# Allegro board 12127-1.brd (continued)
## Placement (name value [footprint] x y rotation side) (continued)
PR106  100KR2F-L1-GP  [R402H16]  127.2 43.27 0 top
PR109  10KR2J-3-GP  [R402H16]  126.03 44.21 180 top
PR110  2D2R5J-1-GP  [R805H24]  124.43 55.85 90 top
PR111  2D2R5J-1-GP  [R805H24]  124.61 49.53 270 top
PR126  10KR2J-3-GP  [R402H16]  115.01 56.31 180 top
PR127  2D2R5J-1-GP  [R805H24]  113.21 55.12 180 top
PR134  100KR2F-L1-GP  [R402H16]  67.59 31.75 90 top
PU8  RT8237CZQW-2-GP  [DFN10G3-G265175H32]  128.8 46.94 180 top
PWCLR1  PIN-CON3-S-GP  [21S-91-03GB01]  107.82 30.48 180 top
Q4  2N7002K-1-GP  [SOT23DGS2D4H44]  111.12 215.26 90 top
Q5  2N7002K-1-GP  [SOT23DGS2D4H44]  116.2 222.5 0 top
Q6  AO3413-GP-U  [SOT23DGS2D8H50]  188.82 223.28 90 top
Q9  AZ5125-02S-R7G-GP  [SOT23-2D4-312H46]  6.68 212.8 180 top
Q10  AZ5125-02S-R7G-GP  [SOT23-2D4-312H46]  6.27 207.09 270 top
Q11  AZ5125-02S-R7G-GP  [SOT23-2D4-312H46]  45.36 219.3 90 top
Q12  MMBT3904-4-GP  [SOT23CBE2D4H44]  84.54 193.53 270 top
Q13  SIR172ADP-T1-GE3-GP  [PPAK-5PH45]  127.43 205.33 0 top
Q14  AZ5125-02S-R7G-GP  [SOT23-2D4-312H46]  44.19 227.79 270 top
Q15  SIRA12DP-T1-GE3-GP  [PPAK-5PH45]  131.98 188.54 90 top
Q16  SIR172ADP-T1-GE3-GP  [PPAK-5PH45]  121.11 205.33 0 top
Q17  AZ5125-02S-R7G-GP  [SOT23-2D4-312H46]  44.17 237.92 90 top
Q22  SIRA12DP-T1-GE3-GP  [PPAK-5PH45]  96.37 194.51 270 top
Q23  SIRA12DP-T1-GE3-GP  [PPAK-5PH45]  96.24 186.06 270 top
Q26  SIR172ADP-T1-GE3-GP  [PPAK-5PH45]  96.55 203 0 top
Q27  SIR172ADP-T1-GE3-GP  [PPAK-5PH45]  165.61 191.85 0 top
Q28  SIRA12DP-T1-GE3-GP  [PPAK-5PH45]  177.11 183.59 90 top
Q29  SIRA12DP-T1-GE3-GP  [PPAK-5PH45]  132.03 197 90 top
Q30  SIRA12DP-T1-GE3-GP  [PPAK-5PH45]  177.11 175.34 90 top
Q31  SIR172ADP-T1-GE3-GP  [PPAK-5PH45]  171.93 191.85 0 top
Q32  SIR172ADP-T1-GE3-GP  [PPAK-5PH45]  102.9 202.98 0 top
Q34  SIR172ADP-T1-GE3-GP  [PPAK-5PH45]  118.82 52.2 180 top
Q35  SIRA12DP-T1-GE3-GP  [PPAK-5PH45]  68.96 48.26 0 top
Q37  MMDT3904-7-F-1-GP  [SOT-363H44]  165.52 160.65 180 top
Q38  2N7002K-2-GP  [SOT23DGS2D4H44]  97.79 48.69 180 top
Q39  AO3413-GP-U  [SOT23DGS2D8H50]  5.99 111.24 0 top
Q40  MMDT3904-7-F-1-GP  [SOT-363H44]  189.52 120.31 90 top
Q42  MMDT3904-7-F-1-GP  [SOT-363H44]  175.97 59.46 180 top
Q43  SIRA12DP-T1-GE3-GP  [PPAK-5PH45]  125.27 60.05 90 top
Q44  MMBT3904-4-GP  [SOT23CBE2D4H44]  8.41 183.64 270 top
Q45  MMBT3904-4-GP  [SOT23CBE2D4H44]  176.89 52.04 0 top
Q46  AO3413-GP-U  [SOT23DGS2D8H50]  171.25 36.58 90 top
Q47  AO3413-GP-U  [SOT23DGS2D8H50]  171.25 32.94 90 top
Q48  MMDT3904-7-F-1-GP  [SOT-363H44]  8.33 179.1 90 top
Q49  MMDT3904-7-F-1-GP  [SOT-363H44]  176.86 36.17 180 top
Q50  MMDT3904-7-F-1-GP  [SOT-363H44]  170.03 49.67 90 top
Q51  QM3006D-GP  [SMD-TO-252-DGS6698H99]  178.46 43.21 90 top
Q53  MMBT3904-4-GP  [SOT23CBE2D4H44]  64.9 58.93 0 top
Q54  2N7002-11-GP  [SOT23DGS2D4H44]  159.33 164.37 270 top
Q55  MMDT3904-7-F-1-GP  [SOT-363H44]  70.99 30.73 0 top
Q56  2N7002-11-GP  [SOT23DGS2D4H44]  161.92 160.8 270 top
Q57  MMBT3904-4-GP  [SOT23CBE2D4H44]  105.13 35.68 90 top
Q58  2N7002K-1-GP  [SOT23DGS2D4H44]  181.99 50.55 0 top
Q59  MMBT3904-4-GP  [SOT23CBE2D4H44]  18.72 15.52 90 top
Q60  MMBT3904-4-GP  [SOT23CBE2D4H44]  22.53 15.52 90 top
Q61  MMBT3904-4-GP  [SOT23CBE2D4H44]  53.77 43.79 0 top
Q62  MMDT3904-7-F-1-GP  [SOT-363H44]  14.07 16.54 270 top
Q64  MMDT3904-7-F-1-GP  [SOT-363H44]  184.53 215.77 180 top
Q67  MMDT3904-7-F-1-GP  [SOT-363H44]  69.93 69.42 180 top
Q69  2N7002DW-6-GP  [SOT-363H44]  137.92 45.85 90 top
Q70  MMBT3904-4-GP  [SOT23CBE2D4H44]  177.57 31.32 90 top
Q71  MMBT3904-4-GP  [SOT23CBE2D4H44]  18.72 11.86 90 top
Q72  MMBT3904-4-GP  [SOT23CBE2D4H44]  22.53 11.86 90 top
Q73  2N7002DW-6-GP  [SOT-363H44]  138.1 42.32 180 top
Q74  MMBT3904-4-GP  [SOT23CBE2D4H44]  188.63 116.88 270 top
Q77  2N7002K-1-GP  [SOT23DGS2D4H44]  60.53 71.62 90 top
Q78  2N7002K-1-GP  [SOT23DGS2D4H44]  64.22 71.62 0 top
Q79  MMBT3904-4-GP  [SOT23CBE2D4H44]  108.97 6.48 90 top
Q80  2N7002K-1-GP  [SOT23DGS2D4H44]  113.79 6.48 90 top
Q82  MMBT3906-4-GP  [SOT23CBE2D4H44]  10.03 55.8 270 top
Q89  AO3401A-GP  [SOT23DGS2D8H50]  158.75 18.16 90 top
Q90  AO3401A-GP  [SOT23DGS2D8H50]  164.59 18.41 0 top
Q108  MMBT3904DW-GP  [SOT-363H44]  5.61 102.59 0 top
Q109  MMBT3904-4-GP  [SOT23CBE2D4H44]  191.64 219.58 0 top
Q110  MMBT3904-4-GP  [SOT23CBE2D4H44]  188.06 219.58 0 top
QF2  MMDT3904-7-F-1-GP  [SOT-363H44]  53.34 18.54 270 top
R3  1KR2J-1-GP  [R402H16]  31.5 221.49 90 top
R4  1KR2J-1-GP  [R402H16]  28.96 221.49 90 top
R5  20KR2F-L-GP  [R402H16]  28.68 233.83 180 top
R6  22KR2J-GP  [R402H16]  31.5 222.63 270 top
R7  22KR2J-GP  [R402H16]  28.96 222.63 270 top
R8  39K2R2F-L-GP  [R402H16]  27.64 233.83 180 top
R9  2K2R2J-2-GP  [R402H16]  31.5 223.77 90 top
R10  2K2R2J-2-GP  [R402H16]  28.96 223.77 90 top
R11  0R0603-PAD-2-GP  [0R0603-PAD-1]  63.37 237.11 90 bottom
R12  20KR2F-L-GP  [R402H16]  21.26 237.97 180 top
R13  100R2F-L1-GP-U  [R402H14]  89.53 231.27 180 top
R14  100R2F-L1-GP-U  [R402H14]  87 228.73 270 top
R15  2K2R2J-2-GP  [R402H16]  84.84 224.41 270 top
R16  2K2R2J-2-GP  [R402H16]  89.03 228.73 270 top
R17  2K2R2J-2-GP  [R402H16]  111.25 223.14 270 top
R18  2K2R2J-2-GP  [R402H16]  113.16 223.14 90 top
R19  2KR2F-3-GP  [R402H16]  185.24 220.47 180 top
R20  20KR2F-L-GP  [R402H16]  16.15 54.46 0 top
R21  1KR2J-1-GP  [R402H16]  183.24 218.47 90 top
R24  10KR2J-3-GP  [R402H16]  10.97 178.38 180 top
R25  5K1R2J-4-GP  [R402H16]  10.97 180.34 180 top
R26  75R2F-2-GP  [R402H16]  35.89 220.5 90 top
R27  4K7R2J-2-GP  [R402H16]  35.89 221.51 90 top
R29  0R3J-0-U-GP  [R603H22]  11.99 224.79 0 top
R30  150R2F-1-GP  [R402H16]  71.88 224.54 90 top
R31  150R2F-1-GP  [R402H16]  74.8 224.54 90 top
R32  150R2F-1-GP  [R402H16]  77.72 224.54 90 top
R33  499R2F-2-GP  [R402H16]  14.73 30.86 270 top
R34  499R2F-2-GP  [R402H16]  14.73 29.84 270 top
R41  100KR2F-L1-GP  [R402H16]  112.39 217.55 90 top
R43  22KR2J-GP  [R402H16]  39.5 225.02 180 top
R44  22KR2J-GP  [R402H16]  40.51 225.02 180 top
R45  2K2R2J-2-GP  [R402H16]  53.21 24.05 180 top
R48  75R2F-2-GP  [R402H16]  33.99 220.5 270 top
R49  4K7R2J-2-GP  [R402H16]  33.99 221.51 270 top
R50  2K2R2J-2-GP  [R402H16]  111.89 222.12 90 top
R51  2K2R2J-2-GP  [R402H16]  110.49 217.55 270 top
R52  75R2F-2-GP  [R402H16]  39.5 222.5 180 top
R53  75R2F-2-GP  [R402H16]  40.51 222.5 180 top
R57  470R2J-2-GP  [R402H16]  100.08 220.66 0 top
R58  470R2J-2-GP  [R402H16]  101.46 220.67 0 top
R59  470R2J-2-GP  [R402H16]  102.64 220.66 0 top
R60  470R2J-2-GP  [R402H16]  103.97 220.67 0 top
R61  470R2J-2-GP  [R402H16]  105.16 220.66 0 top
R62  470R2J-2-GP  [R402H16]  106.54 220.67 0 top
R63  470R2J-2-GP  [R402H16]  107.64 220.66 0 top
R64  470R2J-2-GP  [R402H16]  109.03 220.67 0 top
R65  2K2R2J-2-GP  [R402H16]  83.44 226.57 180 top
R66  2K2R2J-2-GP  [R402H16]  86.74 224.41 270 top
R67  20KR2F-L-GP  [R402H16]  116.08 224.92 270 top
R68  20KR2F-L-GP  [R402H16]  13.65 222.92 0 top
R69  0R3J-0-U-GP  [R603H22]  188.98 225.65 270 top
R70  1KR2J-1-GP  [R402H16]  193.32 223.09 270 top
R71  0R2J-2-GP  [R402H16]  48.13 18.92 270 top
R72  4K7R2J-2-GP  [R402H16]  19.15 29.84 180 top
R73  5K1R2J-4-GP  [R402H16]  14.69 222.92 0 top
R74  33R2J-2-GP  [R402H16]  12.45 228.22 270 top
R75  47R2F-GP  [R402H16]  16.89 211.46 0 top
R76  75R2F-2-GP  [R402H16]  43.26 221.13 90 top
R77  22KR2J-GP  [R402H16]  43.26 222.17 270 top
R78  1MR2J-1-GP  [R402H16]  117.22 220.09 270 top
R79  10KR2F-2-GP  [R402H16]  15.76 222.92 0 top
R80  0R0603-PAD-1-GP  [0R0603-PAD]  159.49 202.44 180 top
R82  1KR2J-1-GP  [R402H16]  188.44 216.76 180 top
R83  4K7R2J-2-GP  [R402H16]  13.34 35.18 0 top
R84  1KR2J-1-GP  [R402H16]  171.07 156.74 90 top
R87  2D2R5J-1-GP  [R805H24]  170.51 166.34 90 top
R88  1KR2J-1-GP  [R402H16]  180.85 167.54 0 top
R90  22KR2J-GP  [R402H16]  15.88 211.46 180 top
R91  75R2F-2-GP  [R402H16]  44.02 215.77 90 top
R92  22KR2J-GP  [R402H16]  43.99 216.81 270 top
R93  120KR2F-L-GP  [R402H16]  187.55 163.74 90 top
R94  120KR2F-L-GP  [R402H16]  187.55 164.76 90 top
R95  120KR2F-L-GP  [R402H16]  187.57 165.78 90 top
R96  10R2F-L-GP  [R402H14]  186.06 161.93 180 top
R97  0R0603-PAD-1-GP  [0R0603-PAD]  12.98 67.23 0 top
R98  10R2F-L-GP  [R402H14]  184.02 161.93 180 top
R99  0R0603-PAD-1-GP  [0R0603-PAD]  40.36 136.14 180 top
R100  10R2F-L-GP  [R402H14]  185.04 161.93 180 top
R102  110R2F-GP  [R402H16]  171.07 160.8 90 top
R103  18KR2F-GP  [R402H16]  183.64 165.81 90 top
R104  0R0603-PAD-1-GP  [0R0603-PAD]  41.68 136.14 180 top
R105  56K2R2F-2-GP  [R402H16]  170.14 154.45 90 top
R106  100KR2F-L1-GP  [R402H16]  193.32 224.13 90 top
R107  4K7R2J-2-GP  [R402H16]  194.84 220.47 180 top
R108  100KR2J-1-GP  [R402H16]  186.99 216.02 270 top
R109  51D1R2F-GP  [R402H16]  170.56 162.46 180 top
R110  0R0603-PAD-2-GP  [0R0603-PAD-1]  12.95 208.71 0 bottom
R111  100R2F-L1-GP-U  [R402H14]  174.35 168.82 90 top
R112  0R2J-2-GP  [R402H16]  171.58 162.46 0 top
R113  75KR2F-GP  [R402H16]  183.16 164.1 180 top
R114  100KR2F-L1-GP  [R402H16]  183.03 158.02 0 top
R115  100KR2F-L1-GP  [R402H16]  181.74 156.46 270 top
R116  1KR2F-3-GP  [R402H16]  175.06 165.77 180 top
R117  0R0603-PAD-2-GP  [0R0603-PAD-1]  63.5 233.17 270 top
R118  47R2F-GP  [R402H16]  14.73 211.46 0 top
R119  100R2F-L1-GP-U  [R402H14]  172.44 168.82 90 top
R120  NTC-220K-5-GP  [NTC-402H24]  170.43 174.12 90 top
R124  0R2J-2-GP  [R402H16]  170.14 155.59 270 top
R126  47D5R2F-1-GP  [R402H16]  175.87 168.12 0 top
R127  0R0402-PAD-1-GP  [0R0402-PAD]  170.43 144.91 270 top
R128  0R0402-PAD-1-GP  [0R0402-PAD]  175.59 150.22 270 top
R129  0R0402-PAD-1-GP  [0R0402-PAD]  170.02 149.78 270 top
R130  22KR2J-GP  [R402H16]  13.72 211.46 180 top
R131  10KR2J-3-GP  [R402H16]  174.24 36.3 270 top
R132  0R2J-2-GP  [R402H16]  169.06 214.02 180 top
R133  8K2R2F-1-GP  [R402H16]  43.81 61.59 0 top
R134  8K2R2J-3-GP  [R402H16]  185.24 213 0 top
R136  0R0402-PAD-1-GP  [0R0402-PAD]  170.05 148.38 270 top
R138  0R0402-PAD-1-GP  [0R0402-PAD]  184.09 121.15 270 top
R139  0R2J-2-GP  [R402H16]  179.78 168.14 180 top
R140  10KR2J-3-GP  [R402H16]  172.44 122.76 0 top
R144  1KR2J-1-GP  [R402H16]  161.67 212.6 180 top
R145  15KR2J-1-GP  [R402H16]  161.19 211.07 90 top
R150  0R0402-PAD-1-GP  [0R0402-PAD]  162.13 207.42 90 top
R153  22R2J-2-GP  [R402H16]  10.21 59.21 90 top
R156  51R2F-2-GP  [R402H16]  188.59 182.45 90 top
R159  150R2F-1-GP  [R402H16]  180.67 119.56 0 top
R162  1MR3F-GP  [R603H22]  177.55 202.44 0 top
R163  6K8R2F-2-GP  [R402H16]  177.55 154.37 180 top
R164  6K8R2F-2-GP  [R402H16]  186.44 157.5 270 top
R165  6K8R2F-2-GP  [R402H16]  184.66 155.47 270 top
R171  0R3J-0-U-GP  [R603H22]  7.24 202.69 270 top
R172  2K49R2F-GP  [R402H16]  173.48 201.9 180 top
R173  -  [0R0805-PAD]  120.68 79.74 180 top
R177  51R2F-2-GP  [R402H16]  144.09 196.52 270 top
R178  -  [0R0805-PAD]  122.05 79.74 180 top
R180  1R5J-2-GP  [R805H24]  132.51 202.18 90 top
R181  10KR2J-3-GP  [R402H16]  131.98 200.69 270 top
R182  2D2R5J-1-GP  [R805H24]  187.86 184.1 270 top
R183  2K2R2J-2-GP  [R402H16]  67.18 68.83 180 top
R184  -  [0R0805-PAD]  123.42 79.74 180 top
R185  -  [0R0805-PAD]  124.79 79.74 180 top
R186  -  [0R0805-PAD]  126.16 79.74 180 top
R187  -  [0R0805-PAD]  116.56 79.74 180 top
R190  1R5J-2-GP  [R805H24]  176.76 179.46 90 top
R193  10KR2J-3-GP  [R402H16]  107.8 198.22 270 top
R195  1R5J-2-GP  [R805H24]  108.08 199.72 90 top
R196  1R5J-2-GP  [R805H24]  132.33 192.81 90 top
R197  10KR2J-3-GP  [R402H16]  176.43 187.5 270 top
R198  0R2J-2-GP  [R402H16]  59.13 68.61 180 top
R200  0R2J-2-GP  [R402H16]  71.25 155.74 90 top
R203  51R2F-2-GP  [R402H16]  83.24 199.14 180 top
R207  NTC-100K-6-GP  [NTC-603H28]  117.07 200.94 0 top
R209  10KR2F-2-GP  [R402H16]  60.18 66.74 180 top
R212  3K9R2F-GP  [R402H16]  178.18 169.61 270 top
R219  20K5R2F-GP  [R402H16]  172.57 154.37 0 top
R220  560KR2F-GP  [R402H16]  175.26 170.46 270 top
R221  69K8R2F-GP  [R402H16]  173.58 154.37 0 top
R222  8K87R2F-2-GP  [R402H16]  58.22 64.81 180 top
R225  59KR2F-GP  [R402H16]  174.6 154.37 0 top
R226  54D9R2F-L1-GP  [R402H16]  171.07 158.77 90 top
R229  0R2J-2-GP  [R402H16]  173.15 165.77 180 top
R231  31K6R2F-GP  [R402H16]  182.83 167.54 180 top
R233  1KR2F-3-GP  [R402H16]  177.41 167.66 270 top
R235  196KR2F-GP  [R402H16]  181.97 163.49 0 top
R239  68KR2F-GP  [R402H16]  175.62 154.37 0 top
R240  100KR2F-L1-GP  [R402H16]  178.97 155.85 270 top
R241  10KR2F-2-GP  [R402H16]  185.8 167.51 180 top
R242  0R2J-2-GP  [R402H16]  183.51 159.64 270 top
R243  0R2J-2-GP  [R402H16]  68.48 30.66 270 top
R245  1R5J-2-GP  [R805H24]  95.71 190.32 270 top
R248  2D2R5J-1-GP  [R805H24]  81.64 198.27 0 top
R251  100R5J-4-GP  [R805H24]  71.12 41.4 180 top
R254  10KR2F-2-GP  [R402H16]  167.64 160.27 180 top
R255  10KR2F-2-GP  [R402H16]  164.21 157.61 90 top
R256  10KR2F-2-GP  [R402H16]  165.99 164.34 0 top
R257  1KR2J-1-GP  [R402H16]  169.9 168.31 180 top
R258  0R2J-2-GP  [R402H16]  164.97 164.34 180 top
R259  2D2R5J-1-GP  [R805H24]  142.6 198.09 270 top
R261  39K2R2F-L-GP  [R402H16]  71.37 34.29 270 top
R263  56R2J-4-GP  [R402H16]  156.08 156.97 270 top
R264  0R0402-PAD-1-GP  [0R0402-PAD]  173.48 140.72 0 top
R265  2R2F-GP  [R402H16]  102.74 80.77 90 top
R266  2D2R5J-1-GP  [R805H24]  190.93 178.07 180 top
R267  2D2R5J-1-GP  [R805H24]  87.1 201.83 270 top
R268  1R5J-2-GP  [R805H24]  176.94 189.15 90 top
R269  0R2J-2-GP  [R402H16]  33.57 174.02 270 top
R270  2D2R5J-1-GP  [R805H24]  146.33 192.81 180 top
R277  3K3R2F-2-GP  [R402H16]  74.55 36.83 0 top
R279  12K4R2F-GP  [R402H16]  73.53 36.83 0 top
R280  -  [0R0805-PAD]  117.93 79.74 180 top
R281  -  [0R0805-PAD]  119.3 79.74 180 top
R282  0R0603-PAD-2-GP  [0R0603-PAD-1]  59.24 77.55 270 top
R283  10KR2F-2-GP  [R402H16]  73.91 40.13 90 top
R284  0R0603-PAD-2-GP  [0R0603-PAD-1]  59.23 76.16 270 top
R286  1KR2F-3-GP  [R402H16]  59.44 80.57 0 top
R287  10R2F-L-GP  [R402H14]  74.12 34.42 270 top
R288  1KR2F-3-GP  [R402H16]  57.94 81.14 270 top
R290  -  [0R0805-PAD]  115.27 79.73 180 top
R293  2D2R5J-1-GP  [R805H24]  71.58 80.14 270 top
R298  1MR2J-1-GP  [R402H16]  163.12 165.57 270 top
R299  1MR2J-1-GP  [R402H16]  163.12 164.53 90 top
R302  10KR2F-2-GP  [R402H16]  107.97 39.86 270 top
R304  0R2J-2-GP  [R402H16]  27.18 165.86 270 top
R305  0R2J-2-GP  [R402H16]  28.57 109.19 90 top
R307  24D9R2F-L-GP  [R402H16]  93.29 158.68 90 top
R311  0R2J-2-GP  [R402H16]  102.65 36.5 180 top
R312  10KR2J-3-GP  [R402H16]  107.57 35.23 0 top
R333  0R2J-2-GP  [R402H16]  58.17 39.5 180 top
R340  51R2F-2-GP  [R402H16]  156.08 155.96 270 top
R341  100R2J-2-GP  [R402H14]  172.9 149.68 0 top
R351  10KR2J-3-GP  [R402H16]  5.66 114.98 270 top
R352  4K7R2J-2-GP  [R402H16]  185.52 110.57 0 top
R353  90D9R2F-1-GP  [R402H16]  171.07 159.79 90 top
R356  20KR2F-L-GP  [R402H16]  185.52 108.64 180 top
R357  0R0402-PAD-2-GP  [0R0402-PAD-1]  188.67 106.63 0 top
R358  8K2R2F-1-GP  [R402H16]  185.04 107.06 270 top
R360  100R2J-2-GP  [R402H14]  188.98 102.72 90 top
R362  2K2R2J-2-GP  [R402H16]  189.41 104.24 0 top
R367  10KR2J-3-GP  [R402H16]  104.65 28.07 90 top
R368  8K2R2F-1-GP  [R402H16]  4.6 99.82 180 top
R369  8K2R2F-1-GP  [R402H16]  5.03 104.98 90 top
R388  10KR2J-3-GP  [R402H16]  44.7 157.61 0 top
R391  0R0402-PAD-1-GP  [0R0402-PAD]  25.91 69.55 90 top
R392  1KR2J-1-GP  [R402H16]  140.34 38.3 0 top
R393  649R2F-GP  [R402H16]  28.66 63.66 180 top
R395  10KR2J-3-GP  [R402H16]  26.24 26.7 0 top
R396  22R2J-2-GP  [R402H16]  10.21 63.37 90 top
R398  10KR2J-3-GP  [R402H16]  50.04 18.92 90 top
R399  8K2R2F-1-GP  [R402H16]  184.15 117.98 90 top
R400  3K9R2F-GP  [R402H16]  184.15 116.97 90 top
R401  100KR2J-1-GP  [R402H16]  187.2 120.78 180 top
R402  10KR2J-3-GP  [R402H16]  191.39 122.43 270 top
R403  10KR2J-3-GP  [R402H16]  36.7 24.89 0 top
R404  20KR2F-L-GP  [R402H16]  185.67 120.78 0 top
R405  10KR2J-3-GP  [R402H16]  37.72 24.89 180 top
R406  22R2J-2-GP  [R402H16]  10.21 61.29 90 top
R407  22R2J-2-GP  [R402H16]  10.21 58.17 90 top
R408  22R2J-2-GP  [R402H16]  10.21 62.33 90 top
R409  0R0603-PAD-1-GP  [0R0603-PAD]  83.79 27.41 0 top
R410  10KR2J-3-GP  [R402H16]  20.32 61.09 90 top
R411  1KR2J-1-GP  [R402H16]  170.43 145.92 270 top
R412  150R2F-1-GP  [R402H16]  31.6 62.53 180 top
R413  1KR2J-1-GP  [R402H16]  20.32 40.21 270 top
R414  10KR2J-3-GP  [R402H16]  108 38.79 270 top
R415  10KR2J-3-GP  [R402H16]  102.67 34.59 180 top
R416  0R0402-PAD-1-GP  [0R0402-PAD]  173.1 139.19 270 top
R417  75R2F-2-GP  [R402H16]  91.82 158.06 180 top
R418  10KR2J-3-GP  [R402H16]  178.19 72.04 270 top
R419  10KR2J-3-GP  [R402H16]  193.17 119.25 270 top
R420  10KR2J-3-GP  [R402H16]  14.58 55.73 180 top
R421  22R2J-2-GP  [R402H16]  10.21 60.25 90 top
R422  10KR2J-3-GP  [R402H16]  127.46 41.81 90 top
R423  1KR2J-1-GP  [R402H16]  14.5 48.49 0 top
R424  75R2F-2-GP  [R402H16]  175.59 149.2 270 top
R425  150R2F-1-GP  [R402H16]  32.77 62.53 180 top
R426  150R2F-1-GP  [R402H16]  30.56 62.53 180 top
R427  10KR2J-3-GP  [R402H16]  20.32 41.22 270 top
R428  15KR2J-1-GP  [R402H16]  178.19 70.11 270 top
R429  0R2J-2-GP  [R402H16]  97.26 46.28 270 top
R430  1MR3F-GP  [R603H22]  41.41 67.56 180 top
R438  4K7R2J-2-GP  [R402H16]  92.41 54.11 0 top
R439  10KR2J-3-GP  [R402H16]  8.89 39.12 90 top
R441  10KR2J-3-GP  [R402H16]  20.5 20.5 90 top
R442  10KR2J-3-GP  [R402H16]  96.98 51.18 270 top
R445  10KR2J-3-GP  [R402H16]  17.78 40.89 0 top
R455  10KR2J-3-GP  [R402H16]  176.91 62.23 0 top
R456  1KR2J-1-GP  [R402H16]  10.16 53.47 90 top
R457  1KR2J-1-GP  [R402H16]  100.2 63.4 90 top
R458  1KR2J-1-GP  [R402H16]  48.13 17.91 90 top
R459  20KR2F-L-GP  [R402H16]  173.48 60.07 270 top
R464  10KR2J-3-GP  [R402H16]  179.1 36.45 180 top
R465  10KR2J-3-GP  [R402H16]  179.1 38.35 0 top
R466  10KR2J-3-GP  [R402H16]  177.44 38.73 90 top
R467  10KR2J-3-GP  [R402H16]  175.69 55.54 0 top
R468  8K2R2F-1-GP  [R402H16]  180.49 33.91 270 top
R469  1KR2J-1-GP  [R402H16]  177.16 55.37 90 top
R470  4K7R2J-2-GP  [R402H16]  105.33 52.48 180 top
R471  8K2R2F-1-GP  [R402H16]  174.24 37.34 90 top
R472  0R2J-2-GP  [R402H16]  105.41 54.46 0 top
R476  1KR2J-1-GP  [R402H16]  105.08 65.56 180 top
R477  1KR2J-1-GP  [R402H16]  174.12 48.64 270 top
R478  33R2J-2-GP  [R402H16]  27.3 163.19 90 top
R481  20KR2F-L-GP  [R402H16]  119.76 26.12 180 top
R482  90D9R2F-1-GP  [R402H16]  168.14 148.37 90 top
R483  0R0402-PAD-2-GP  [0R0402-PAD-1]  39.31 21.27 90 top
R484  1KR2J-1-GP  [R402H16]  97.71 22.99 180 top
R485  10KR2J-3-GP  [R402H16]  174.12 50.67 90 top
R486  10KR2J-3-GP  [R402H16]  167.06 50.11 0 top
R488  33R2J-2-GP  [R402H16]  43.31 186.06 0 top
R489  0R0402-PAD-2-GP  [0R0402-PAD-1]  184.4 49.53 180 top
R491  10KR2J-3-GP  [R402H16]  174.12 49.66 270 top
R492  4K7R2J-2-GP  [R402H16]  120.22 27.68 90 top
R493  0R0402-PAD-2-GP  [0R0402-PAD-1]  35.44 19.89 90 top
R494  390KR2J-GP  [R402H16]  25.2 26.7 180 top
R495  22KR2J-GP  [R402H16]  184.4 51.44 0 top
R496  0R0402-PAD-2-GP  [0R0402-PAD-1]  13.41 28.32 270 top
R497  0R2J-2-GP  [R402H16]  118.24 27.65 90 top
R498  4K7R2J-2-GP  [R402H16]  118.69 26.12 0 top
R499  20KR2F-L-GP  [R402H16]  116.28 26.65 90 top
R502  1MR2J-1-GP  [R402H16]  23.62 32 270 top
R504  1KR2J-1-GP  [R402H16]  88.01 25.17 180 top
R505  33R2J-2-GP  [R402H16]  78.36 27.61 0 top
R507  1KR2J-1-GP  [R402H16]  82.14 28.07 270 top
R508  10KR2J-3-GP  [R402H16]  29.21 31.39 0 top
R512  33R2J-2-GP  [R402H16]  82.83 51.61 0 top
R514  1KR2J-1-GP  [R402H16]  20.27 35.94 90 top
R515  390KR2J-GP  [R402H16]  20.27 34.92 90 top
R516  44D2R2F-GP  [R402H16]  173.97 149.68 0 top
R518  1KR2F-3-GP  [R402H16]  174.55 122.74 0 top
R519  1KR2J-1-GP  [R402H16]  173.52 122.75 180 top
R521  0R0402-PAD-2-GP  [0R0402-PAD-1]  32.11 27.38 0 top
R523  0R0402-PAD-2-GP  [0R0402-PAD-1]  33.12 27.38 0 top
R524  10KR2J-3-GP  [R402H16]  15.98 48.06 270 top
R525  1KR2J-1-GP  [R402H16]  5.97 184.53 180 top
R526  2K2R2J-2-GP  [R402H16]  101.85 25.93 180 top
R532  -  [0R0805-PAD]  63.45 41.1 0 top
R533  0R0402-PAD-1-GP  [0R0402-PAD]  10.92 184.78 180 top
R534  10KR2J-3-GP  [R402H16]  11.58 46.96 90 top
R535  2K2R2J-2-GP  [R402H16]  100.84 25.93 180 top
R536  10KR2J-3-GP  [R402H16]  17.68 29.39 90 top
R537  124R2F-U-GP  [R402H16]  176.78 20.83 180 top
R538  1KR2J-1-GP  [R402H16]  45.72 31.5 0 top
R541  100R2F-L1-GP-U  [R402H14]  91.21 159.56 90 top
R542  33R2J-2-GP  [R402H16]  88.75 51.51 0 top
R546  2K2R2J-2-GP  [R402H16]  12.83 29.84 90 top
R547  7K5R2F-1DL-GP  [R402H16]  41.4 62.1 270 top
R548  -  [0R0805-PAD]  62.13 41.1 0 top
R549  220R5J-GP  [R805H24]  180.37 25.07 0 top
R550  0R5J-5-GP  [R805H24]  167.51 18.62 180 top
R551  0R5J-5-GP  [R805H24]  158.85 22.15 270 top
R552  0R2J-2-GP  [R402H16]  14.63 49.96 90 top
R553  10MR3J-L1-GP  [R603H22]  22.53 24.33 0 top
R554  100R2J-2-GP  [R402H14]  18.97 18.92 0 top
R555  0R5J-5-GP  [R805H24]  8.79 111.76 180 top
R556  10KR2J-3-GP  [R402H16]  106.43 9.27 90 top
R559  210R2F-L-GP  [R402H16]  176.78 23.62 180 top
R560  10KR2J-3-GP  [R402H16]  20.5 19.38 90 top
R561  0R0402-PAD-1-GP  [0R0402-PAD]  10.92 182.88 0 top
R562  10KR2J-3-GP  [R402H16]  65.18 15.8 0 top
R563  10KR2J-3-GP  [R402H16]  26.29 31.37 0 top
R564  10KR2J-3-GP  [R402H16]  57.3 26.16 0 top
R565  10KR2J-3-GP  [R402H16]  37.47 28.07 0 top
R566  10KR2J-3-GP  [R402H16]  54.23 31.11 90 top
R567  -  [0R0805-PAD]  64.77 41.1 0 top
R568  -  [0R0402-PAD]  90.42 13.34 90 top
R570  10KR2J-3-GP  [R402H16]  92.76 14.78 0 top
R571  10KR2J-3-GP  [R402H16]  35.18 24.38 90 top
R572  20KR2J-L2-GP  [R402H16]  91.03 17.86 0 top
R573  10KR2J-3-GP  [R402H16]  35.18 25.4 270 top
R574  10KR2J-3-GP  [R402H16]  19.58 28.37 270 top
R576  7K5R2F-1DL-GP  [R402H16]  49.33 37.85 90 top
R577  1KR2J-1-GP  [R402H16]  47.75 31.5 180 top
R578  0R2J-2-GP  [R402H16]  78.99 19.3 90 top
R579  0R2J-2-GP  [R402H16]  11.81 35.56 90 top
R580  10KR2J-3-GP  [R402H16]  54.86 26.14 0 top
R581  0R0402-PAD-1-GP  [0R0402-PAD]  26.52 21.21 180 top
R583  10KR2J-3-GP  [R402H16]  49.91 29.08 180 top
R584  10KR2J-3-GP  [R402H16]  15.49 40.26 270 top
R585  10KR2J-3-GP  [R402H16]  49.78 31.5 0 top
R590  10KR2J-3-GP  [R402H16]  30.86 25.1 180 top
R593  10KR2J-3-GP  [R402H16]  52.2 24.05 180 top
R594  10KR2J-3-GP  [R402H16]  33.4 31.39 0 top
R595  10KR2J-3-GP  [R402H16]  53.24 26.14 0 top
R596  10KR2J-3-GP  [R402H16]  17.27 45.14 270 top
R597  10KR2J-3-GP  [R402H16]  46.74 31.5 180 top
R598  1KR2J-1-GP  [R402H16]  51.79 25.7 270 top
R599  1KR2J-1-GP  [R402H16]  12.95 69.6 0 top
R600  -  [0R0402-PAD]  89.66 8.13 270 top
R601  1KR2J-1-GP  [R402H16]  90.42 14.35 270 top
R602  10KR2J-3-GP  [R402H16]  89.92 15.8 180 top
R604  4K7R2J-2-GP  [R402H16]  90.53 19.33 270 top
R605  10KR2J-3-GP  [R402H16]  90.53 20.35 90 top
R606  10KR2J-3-GP  [R402H16]  74.3 29.51 270 top
R607  10KR2J-3-GP  [R402H16]  68.48 29.59 90 top
R609  10KR2J-3-GP  [R402H16]  48.9 29.08 180 top
R610  33R2J-2-GP  [R402H16]  84.2 51.61 0 top
R612  33R2J-2-GP  [R402H16]  89.79 51.51 0 top
R613  10KR2J-3-GP  [R402H16]  48.77 31.5 0 top
R615  10KR2J-3-GP  [R402H16]  14.38 36.2 180 top
R616  10KR2J-3-GP  [R402H16]  54.56 15.77 180 top
R617  22D6R2F-L1-GP  [R402H16]  17.17 54.46 180 top
R618  1KR2J-1-GP  [R402H16]  13.56 54.94 0 top
R619  10KR2J-3-GP  [R402H16]  44.7 31.5 0 top
R620  10KR2J-3-GP  [R402H16]  51.18 24.05 0 top
R621  10KR2J-3-GP  [R402H16]  32.38 31.39 0 top
R623  10KR2J-3-GP  [R402H16]  74.27 31.6 270 top
R624  1KR2J-1-GP  [R402H16]  108 36.75 90 top
R625  10KR2J-3-GP  [R402H16]  26.8 16 180 top
R627  1KR2J-1-GP  [R402H16]  108 37.77 270 top
R629  33R2J-2-GP  [R402H16]  89 27.84 0 top
R630  1KR2J-1-GP  [R402H16]  92.58 28.19 270 top
R631  1KR2J-1-GP  [R402H16]  89.05 25.17 180 top
R632  33R2J-2-GP  [R402H16]  27.81 16 180 top
R633  680R2J-3-GP  [R402H16]  96.7 22.99 180 top
R634  10KR2J-3-GP  [R402H16]  95.68 22.99 180 top
R635  1KR2J-1-GP  [R402H16]  95 5.54 0 top
R636  10KR2J-3-GP  [R402H16]  10.16 52.45 270 top
R637  0R0402-PAD-1-GP  [0R0402-PAD]  190.75 139.83 270 top
R638  4K7R2J-2-GP  [R402H16]  27.74 10.92 180 top
R639  51R2F-2-GP  [R402H16]  177.1 146.83 0 top
R640  51R2F-2-GP  [R402H16]  176.64 145.35 90 top
R641  680R2J-3-GP  [R402H16]  98.96 23.42 180 top
R642  10KR2J-3-GP  [R402H16]  99.97 23.42 180 top
R643  8K2R2F-1-GP  [R402H16]  96.06 5.54 0 top
R644  220R5J-GP  [R805H24]  14.99 12.93 270 top
R646  1KR2J-1-GP  [R402H16]  28.19 31.39 0 top
R647  10KR2J-3-GP  [R402H16]  13.59 42.55 90 top
R648  10KR2J-3-GP  [R402H16]  61.54 59.79 90 top
R649  1KR2J-1-GP  [R402H16]  56.52 24.26 180 top
R650  10KR2J-3-GP  [R402H16]  46.86 29.08 180 top
R651  10KR2J-3-GP  [R402H16]  47.88 29.08 0 top
R652  33R2J-2-GP  [R402H16]  8.89 45.85 90 top
R653  75R3J-L-GP  [R603H22]  68.61 59.18 0 top
R654  75R3J-L-GP  [R603H22]  67.34 59.18 0 top
R655  1KR2J-1-GP  [R402H16]  34.8 30.1 180 top
R656  1KR2J-1-GP  [R402H16]  17.68 32.69 0 top
R657  680R2J-3-GP  [R402H16]  98.78 25.93 180 top
R658  10KR2J-3-GP  [R402H16]  99.8 25.93 180 top
R659  10KR2J-3-GP  [R402H16]  5.97 182.63 0 top
R660  1KR2J-1-GP  [R402H16]  176.54 139.69 90 top
R661  51R2F-2-GP  [R402H16]  176.64 144.19 90 top
R662  10KR2J-3-GP  [R402H16]  25.4 10.54 270 top
R663  51R2F-2-GP  [R402H16]  190.65 143.46 270 top
R664  1KR2F-3-GP  [R402H16]  172.66 84.22 180 top
R665  1KR2F-3-GP  [R402H16]  173.77 84.23 0 top
R666  -  [0R0402-PAD]  97.16 5.59 180 top
R667  0R2J-2-GP  [R402H16]  101.6 22.99 180 top
R668  20KR2J-L2-GP  [R402H16]  113.41 13.21 0 top
R669  10KR2J-3-GP  [R402H16]  94.67 22.99 0 top
R670  10KR2J-3-GP  [R402H16]  25.78 16 180 top
R671  4K7R2J-2-GP  [R402H16]  27.3 13.89 270 top
R672  10KR2J-3-GP  [R402H16]  25.4 13.72 90 top
R673  0R2J-2-GP  [R402H16]  102.62 22.99 180 top
R674  -  [0R0402-PAD]  98.17 5.59 180 top
R676  10KR2J-3-GP  [R402H16]  34.8 27.56 0 top
R677  0R2J-2-GP  [R402H16]  54.18 56.32 0 top
R678  0R2J-2-GP  [R402H16]  54.18 53.71 180 top
R679  10KR2J-3-GP  [R402H16]  15.42 36.73 180 top
R680  100R2F-L1-GP-U  [R402H14]  99.69 6.1 90 top
R681  0R2J-2-GP  [R402H16]  55.22 56.33 0 top
R682  10KR2F-2-GP  [R402H16]  163.3 14.58 180 top
R683  10KR2J-3-GP  [R402H16]  49.89 27.48 90 top
R684  10KR2F-2-GP  [R402H16]  106.68 22.99 180 top
R685  10KR2J-3-GP  [R402H16]  49.89 26.47 90 top
R687  10KR2J-3-GP  [R402H16]  45.97 25.27 0 top
R688  10KR2J-3-GP  [R402H16]  181.23 52.96 90 top
R689  0R2J-2-GP  [R402H16]  55.22 53.71 180 top
R690  0R2J-2-GP  [R402H16]  57.18 56.21 0 top
R691  0R2J-2-GP  [R402H16]  57.18 53.67 180 top
R692  0R2J-2-GP  [R402H16]  58.2 56.21 0 top
R693  10KR2F-2-GP  [R402H16]  108.71 22.99 180 top
R694  7K5R2F-1DL-GP  [R402H16]  41.4 61.09 90 top
R695  7K5R2F-1DL-GP  [R402H16]  49.2 51.77 270 top
R696  1KR2J-1-GP  [R402H16]  111.38 7.29 0 top
R697  7K5R2F-1DL-GP  [R402H16]  50.16 48.13 270 top
R698  10KR2J-3-GP  [R402H16]  17.68 28.37 270 top
R699  0R2J-2-GP  [R402H16]  58.2 53.67 180 top
R701  1KR2J-1-GP  [R402H16]  57.53 24.26 0 top
R702  0R0402-PAD-1-GP  [0R0402-PAD]  88.39 15.42 90 top
R703  10KR2F-2-GP  [R402H16]  111.76 22.99 180 top
R704  1KR2F-3-GP  [R402H16]  100.71 80.82 90 top
R705  0R2J-2-GP  [R402H16]  186.99 217.04 270 top
R707  10KR2J-3-GP  [R402H16]  50.04 17.91 90 top
R708  0R0402-PAD-1-GP  [0R0402-PAD]  90.02 17.86 0 top
R709  4K7R2J-2-GP  [R402H16]  155.98 15.8 270 top
R710  2KR2F-3-GP  [R402H16]  110.74 22.99 180 top
R711  2K1R2F-GP  [R402H16]  161.29 18.29 0 top
R712  10KR2J-3-GP  [R402H16]  63.02 15.8 0 top
R713  10KR2J-3-GP  [R402H16]  8.84 104.75 90 top
R717  1KR2J-1-GP  [R402H16]  99.69 5.08 270 top
R720  -  [0R0402-PAD]  102.49 5.59 0 top
R722  1KR3J-L1-GP  [R603H22]  11.68 11.3 180 top
R723  15KR2J-1-GP  [R402H16]  113.41 20.32 0 top
R727  4K7R2J-2-GP  [R402H16]  103.5 5.59 180 top
R729  10KR2F-2-GP  [R402H16]  111.89 20.65 270 top
R730  2K7R2J-GP  [R402H16]  138.94 47.88 270 top
R733  -  [0R0402-PAD]  109.98 13.72 90 top
R734  220R5J-GP  [R805H24]  14.99 10.92 270 top
R736  4K7R2J-2-GP  [R402H16]  171.07 38.89 90 top
R737  1KR2J-1-GP  [R402H16]  25.4 11.56 90 top
R738  10KR2F-2-GP  [R402H16]  109.98 17.78 90 top
R739  4K99R2F-L-GP  [R402H16]  109.98 18.8 90 top
R747  5K6R2J-1-GP  [R402H16]  180.9 32.46 180 top
R751  8K2R2F-1-GP  [R402H16]  137.03 47.88 270 top
R752  8K2R2F-1-GP  [R402H16]  140.21 46.35 0 top
R754  1KR2J-1-GP  [R402H16]  109.98 8.76 90 top
R755  10KR2J-3-GP  [R402H16]  106.05 7.11 270 top
R756  1KR2J-1-GP  [R402H16]  109.98 12.7 90 top
R757  1KR2J-1-GP  [R402H16]  112.39 13.21 0 top
R759  0R2J-2-GP  [R402H16]  31.9 23.9 180 top
R760  4K7R2J-2-GP  [R402H16]  27.3 12.88 270 top
R761  0R0402-PAD-1-GP  [0R0402-PAD]  54.86 24 180 top
R762  10KR2J-3-GP  [R402H16]  180.87 30.48 180 top
R764  100R2F-L1-GP-U  [R402H14]  59.86 15.79 0 top
R765  20KR2F-L-GP  [R402H16]  64.08 15.8 180 top
R766  200R2F-L-GP  [R402H16]  58.79 15.8 180 top
R767  1KR2J-1-GP  [R402H16]  25.4 12.7 90 top
R768  2K7R2J-GP  [R402H16]  135.64 45.34 0 top
R769  1KR2F-3-GP  [R402H16]  175.16 30.48 180 top
R772  0R0805-PAD-1-GP  [0R0805-PAD]  30.76 68.63 90 top
R773  1KR2J-1-GP  [R402H16]  140.21 44.32 0 top
R774  -  [0R0402-PAD]  109.98 14.73 270 top
R775  -  [0R0402-PAD]  109.98 15.75 270 top
R776  10KR2J-3-GP  [R402H16]  134.62 41.27 180 top
R777  10KR2J-3-GP  [R402H16]  27.86 239.42 90 top
R778  10KR2J-3-GP  [R402H16]  136.35 39.65 90 top
R788  10KR2J-3-GP  [R402H16]  67.06 72.52 0 top
R789  10KR2J-3-GP  [R402H16]  72.26 69.09 180 top
R790  1KR2J-1-GP  [R402H16]  65.46 68.76 0 top
R791  10KR2J-3-GP  [R402H16]  57.15 64.82 180 top
R792  1KR2J-1-GP  [R402H16]  63.11 68.16 270 top
R793  24D9R2F-L-GP  [R402H16]  171.96 120.27 90 top
R794  10KR2J-3-GP  [R402H16]  179.62 119.56 180 top
R795  10KR2J-3-GP  [R402H16]  173.23 147.5 180 top
R796  100R2F-L1-GP-U  [R402H14]  90.78 158.06 180 top
R797  49D9R2F-GP  [R402H16]  156.46 158.5 0 top
R798  49D9R2F-GP  [R402H16]  71.6 160.73 270 top
R799  49D9R2F-GP  [R402H16]  173.61 167.77 270 top
R800  110R2F-GP  [R402H16]  168.09 149.79 90 top
R804  49D9R2F-GP  [R402H16]  71.58 159.66 270 top
R805  24D9R2F-L-GP  [R402H16]  93.29 157.64 90 top
R806  0R2J-2-GP  [R402H16]  180.72 117.6 180 top
R807  0R2J-2-GP  [R402H16]  73.05 158.12 0 top
R808  0R2J-2-GP  [R402H16]  177.04 149.66 0 top
R810  1KR2J-1-GP  [R402H16]  27.53 21.21 180 top
R811  200R2F-L-GP  [R402H16]  56.63 15.77 180 top
R812  100R2F-L1-GP-U  [R402H14]  57.7 15.79 0 top
R816  51R2F-2-GP  [R402H16]  56.64 17.74 180 top
R817  200R2F-L-GP  [R402H16]  60.92 15.8 180 top
R818  100R2F-L1-GP-U  [R402H14]  55.59 15.79 0 top
R819  0R0402-PAD-1-GP  [0R0402-PAD]  190.75 141.22 270 top
R820  0R0402-PAD-1-GP  [0R0402-PAD]  190.65 146.44 270 top
R821  0R0402-PAD-1-GP  [0R0402-PAD]  190.65 145.42 270 top
R823  0R2J-2-GP  [R402H16]  175.16 33.17 0 top
R824  0R2J-2-GP  [R402H16]  174.14 33.17 180 top
R826  1KR2J-1-GP  [R402H16]  190.6 130.8 270 top
R827  1KR2J-1-GP  [R402H16]  190.6 131.82 270 top
R828  1KR2J-1-GP  [R402H16]  190.6 132.83 270 top
R829  1KR2J-1-GP  [R402H16]  190.6 133.85 270 top
R830  1KR2J-1-GP  [R402H16]  190.6 134.87 270 top
R831  1KR2J-1-GP  [R402H16]  190.6 135.88 270 top
R832  1KR2J-1-GP  [R402H16]  190.6 136.9 270 top
R833  1KR2J-1-GP  [R402H16]  190.6 137.91 270 top
R834  1KR2J-1-GP  [R402H16]  176.64 128.89 90 top
R835  1KR2J-1-GP  [R402H16]  176.64 129.91 90 top
R836  1KR2J-1-GP  [R402H16]  176.64 130.93 90 top
R837  1KR2J-1-GP  [R402H16]  176.64 131.94 90 top
R838  1KR2J-1-GP  [R402H16]  176.64 135.04 90 top
R839  1KR2J-1-GP  [R402H16]  176.52 137.63 90 top
R840  1KR2J-1-GP  [R402H16]  39.75 23.5 0 top
R841  1KR2J-1-GP  [R402H16]  18.8 40.39 0 top
R842  1KR2J-1-GP  [R402H16]  176.53 138.66 90 top
R843  1KR2J-1-GP  [R402H16]  176.66 136.14 90 top
R844  1KR2J-1-GP  [R402H16]  176.64 126.86 90 top
R845  1KR2J-1-GP  [R402H16]  176.64 127.88 90 top
R846  1KR2J-1-GP  [R402H16]  7.21 57.53 0 top
R847  0R2J-2-GP  [R402H16]  7.62 55.63 180 top
R848  1KR2J-1-GP  [R402H16]  176.64 132.98 90 top
R849  1KR2J-1-GP  [R402H16]  176.64 134.03 90 top
R850  33R2J-2-GP  [R402H16]  27.08 65.53 180 top
R851  0R0402-PAD-1-GP  [0R0402-PAD]  102.74 79.76 90 top
R852  33R2J-2-GP  [R402H16]  26.04 65.53 180 top
R853  1KR2F-3-GP  [R402H16]  100.71 79.81 270 top
R854  0R0402-PAD-1-GP  [0R0402-PAD]  175.26 84.71 90 top
R855  2R2F-GP  [R402H16]  177.16 83.82 270 top
R856  24D9R2F-L-GP  [R402H16]  175.26 82.68 270 top
R857  1KR2F-3-GP  [R402H16]  171.59 84.22 180 top
R858  0R0402-PAD-1-GP  [0R0402-PAD]  169.04 84.58 270 top
R859  1KR2F-3-GP  [R402H16]  170.56 84.2 0 top
R863  2R2F-GP  [R402H16]  167.13 83.57 90 top
R864  24D9R2F-L-GP  [R402H16]  164.41 83.29 90 top
R865  1KR2J-1-GP  [R402H16]  114.17 9.27 0 top
R866  0R0402-PAD-2-GP  [0R0402-PAD-1]  104.52 5.59 0 top
R867  1KR2J-1-GP  [R402H16]  192.02 148.34 90 top
R1248  0R2J-2-GP  [R402H16]  90.81 161.09 0 top
R1549  47KR2J-2-GP  [R402H16]  16.46 35.74 0 top
R2215  1K5R2F-2-GP  [R402H16]  38.73 23.5 0 top
R2216  51R2F-2-GP  [R402H16]  173.46 142.69 0 top
R2217  825R2F-GP  [R402H16]  177.27 142.69 180 top
R2218  249R2F-GP  [R402H16]  175.19 142.69 0 top
R2219  100R2F-L1-GP-U  [R402H14]  176.23 142.69 180 top
R2220  22KR2J-GP  [R402H16]  63.18 69.22 270 top
R2225  5D11R2F-GP  [R402H16]  12.7 33.48 270 top
R2226  3K3R2F-2-GP  [R402H16]  184.1 120.09 270 top
R2227  1K8R2F-GP  [R402H16]  184.1 119.05 90 top
R2230  6K04R2F-GP  [R402H16]  72.93 145.88 0 top
R2231  2K67R2F-2-GP  [R402H16]  73.98 145.87 180 top
R2233  11K8R2F-GP  [R402H16]  162.31 157.61 270 top
R2234  5K1R2J-4-GP  [R402H16]  11.68 16.76 180 top
R2235  5K1R2J-4-GP  [R402H16]  13.21 14.48 90 top
R2236  5K1R2J-4-GP  [R402H16]  11.68 14.86 180 top
R2237  4K7R2J-2-GP  [R402H16]  181.53 37.92 90 top
R2238  30KR2J-4-GP  [R402H16]  180.49 34.92 90 top
R2239  10KR2J-3-GP  [R402H16]  7.52 105.79 270 top
R2240  39K2R2F-L-GP  [R402H16]  5.54 107.31 180 top
R2243  8K2R2F-1-GP  [R402H16]  15.65 42.01 270 top
R2246  2D2R3J-2-GP  [R603H22]  68.4 39.17 180 top
RJ45  SKT-RJ45-USB-9-GP  [RU4-161A9WGF]  170.13 224.57 180 top
RN2  SRN8K2J-4-GP  [ARES8-CN24H20]  11.3 40.13 180 top
RN3  SRN8K2J-4-GP  [ARES8-CN24H20]  14.22 46.1 90 top
RN7  SRN8K2J-4-GP  [ARES8-CN24H20]  109.98 10.67 270 top
RN22  SRN1KJ-7-GP  [SMD-ARES4H18]  7.04 175.97 0 top
RN31  SRN10KJ-5-GP  [ARES2H18]  50.42 53.37 270 top
RN32  SRN10KJ-5-GP  [ARES2H18]  53.59 29.46 270 top
RN33  SRN10KJ-5-GP  [ARES2H18]  53.85 48.51 90 top
RN34  SRN10KJ-5-GP  [ARES2H18]  19.68 56.52 90 top
RN35  SRN10KJ-5-GP  [ARES2H18]  11.43 38.1 90 top
RN36  SRN10KJ-5-GP  [ARES2H18]  30.78 31.06 180 top
RN40  SRN10KJ-5-GP  [ARES2H18]  105.84 61.04 180 top
RN41  SRN10KJ-5-GP  [ARES2H18]  107.87 61.04 180 top
RN42  SRN10KJ-5-GP  [ARES2H18]  27.75 26.63 0 top
RN46  SRN33J-7-GP-U  [ARES8-CN24-UH20]  14.55 52.58 270 top
RN57  SRN33J-5-GP-U  [SMD-ARES4H18]  9.32 43.59 0 top
RN58  SRN33J-5-GP-U  [SMD-ARES4H18]  11.35 49.4 0 top
RN60  SRN33J-5-GP-U  [SMD-ARES4H18]  79.88 27.05 180 top
RN62  SRN33J-5-GP-U  [SMD-ARES4H18]  90.58 27.15 180 top
RN64  SRN10KJ-5-GP  [ARES2H18]  49.56 24.1 180 top
RN65  SRN8K2J-3-GP  [SMD-ARES4]  16.13 43.59 90 top
RN66  SRN10KJ-5-GP  [ARES2H18]  47.51 25.04 180 top
SATA0  SKT-SATA7P-68-GP  [ABA-SAT-010-K50]  99.29 75.46 180 top
SATA1  SKT-SATA7P-29-GP-U  [ABA-SAT-010-K04-U]  80 75.46 180 top
SLOT1  TYCO-CONN36-4R-1GP  [1-1470780-7]  37.7 186.9 270 top
SLOT2  T-CONN164-4R4-GP  [4-1470780-7]  17.4 186.9 270 top
SR732  -  [0R0402-PAD]  93.01 21.77 90 top
TC1  E560U6D3VM-3-GP  [ECAP-100D6D3H375]  108.51 181.48 0 top
TC2  E560U6D3VM-3-GP  [ECAP-100D6D3H375]  116.46 181.5 0 top
TC3  E560U6D3VM-3-GP  [ECAP-100D6D3H375]  124.53 181.55 0 top
TC4  E100U16VM-22-GP  [ECAP-100D6D3H237]  22.48 216.53 270 top
TC5  E100U16VM-22-GP  [ECAP-100D6D3H237]  38.99 216.66 270 top
TC6  E100U16VM-22-GP  [ECAP-100D6D3H237]  30.35 216.66 270 top
TC7  E100U16VM-22-GP  [ECAP-100D6D3H237]  14.61 216.53 270 top
TC9  E270U16VM-16-GP  [ECAP-138D8-UH355]  110.87 205.36 270 top
TC10  E560U6D3VM-3-GP  [ECAP-100D6D3H375]  132.36 181.46 0 top
TC11  E470U16VM-L8-GP  [ECAP-138D8H512]  27.3 203.2 0 top
TC12  E560U6D3VM-3-GP  [ECAP-100D6D3H375]  158.01 175.72 0 top
TC13  E100U16VM-25-GP  [ECAP-80D5H493]  26.04 195.02 0 top
TC15  E820U2D5VM-6-GP  [ECAP-100D6D3H375]  112.5 74.4 270 top
TC22  E820U2D5VM-6-GP  [ECAP-100D6D3H375]  61.21 46.86 0 top
TC29  E560U6D3VM-3-GP  [ECAP-100D6D3H375]  112.24 45.06 270 top
TC34  E270U16VM-16-GP  [ECAP-138D8-UH355]  143.64 204.42 270 top
TC38  E220U16VM-25-GP  [ECAP-100D6D3H473]  183.82 13.23 270 top
TC40  E270U16VM-16-GP  [ECAP-138D8-UH355]  180.16 194.87 0 top
TC41  E560U6D3VM-3-GP  [ECAP-100D6D3H375]  120.37 44.96 270 top
TC42  E820U2D5VM-6-GP  [ECAP-100D6D3H375]  123.95 73.84 270 top
TC45  E820U2D5VM-6-GP  [ECAP-100D6D3H375]  126.31 107.82 0 top
TP1  -  [TPAD24]  27.43 230.89 0 top
TP2  -  [TPAD28]  91.95 226.44 0 top
TP3  -  [TPAD24]  167.97 202.92 0 top
TP4  -  [TPAD24]  166.65 202.92 0 top
TP5  -  [TPAD24]  169.29 202.92 0 top
TP6  -  [TPAD24]  103.17 63.37 180 top
TP7  -  [TPAD24]  101.85 63.4 180 top
TP10  -  [TPAD24]  141.02 40.74 90 top
TP32  -  [TPAD24]  116.71 122.17 180 bottom
TP33  -  [TPAD24]  122.99 129.35 180 bottom
TP34  -  [TPAD24]  107.53 129.2 180 bottom
TP35  -  [TPAD24]  94.74 167.64 180 bottom
TP36  -  [TPAD24]  93.47 168.4 180 bottom
TP40  -  [TPAD24]  13.46 231.27 0 top
TP41  -  [TPAD24]  32.13 42.8 180 bottom
TP42  -  [TPAD24]  140.13 35.69 0 top
TP48  -  [TPAD24]  19.74 236.96 0 top
TP49  -  [TPAD24]  30.02 46.66 180 bottom
TP50  -  [TPAD24]  16.92 50.22 0 top
TP51  -  [TPAD24]  36.57 47.88 180 bottom
TP53  -  [TPAD24]  20.62 49.05 0 top
TP56  -  [TPAD24]  18.54 50.22 0 top
TP66  -  [TPAD24]  36.45 36.2 180 bottom
TP67  -  [TPAD24]  36.35 38.38 180 bottom
TP68  -  [TPAD24]  36.27 42.67 180 bottom
TP76  -  [TPAD24]  107.19 157.32 180 bottom
TP77  -  [TPAD24]  105.74 157.58 180 bottom
TP78  -  [TPAD24]  95.89 168.66 180 bottom
TP79  -  [TPAD24]  97.42 168.75 180 bottom
TP80  -  [TPAD24]  113.44 158.24 180 bottom
TP85  -  [TPAD24]  25.91 36.5 180 bottom
TP86  -  [TPAD24]  34.75 42.14 180 bottom
TP87  -  [TPAD28]  57.86 18.47 0 top
TP88  -  [TPAD24]  18.69 34.85 0 top
TP90  -  [TPAD24]  41.68 33.71 180 bottom
TP103  -  [TPAD28]  157.99 160.02 180 bottom
TP104  -  [TPAD28]  59.18 18.47 0 top
TP105  -  [TPAD28]  60.43 18.47 0 top
TP107  -  [TPAD28]  156.46 160.02 180 bottom
TP108  -  [TPAD28]  157.99 158.62 180 bottom
TP109  -  [TPAD28]  156.51 158.6 180 bottom
TP110  -  [TPAD28]  153.67 158.62 180 bottom
TP111  -  [TPAD28]  128.56 157.16 180 bottom
TP112  -  [TPAD28]  126.64 150.77 180 bottom
TP113  -  [TPAD28]  156.54 155.8 180 bottom
TP116  -  [TPAD28]  103.61 149.67 180 bottom
TP117  -  [TPAD28]  103.44 154.78 180 bottom
TP118  -  [TPAD28]  103.97 157.27 180 bottom
TP119  -  [TPAD28]  104.93 154.7 180 bottom
TP120  -  [TPAD28]  105.82 156.2 180 bottom
TP121  -  [TPAD28]  103.54 151.02 180 bottom
TP122  -  [TPAD28]  126.6 153.68 180 bottom
TP123  -  [TPAD28]  127.41 156.35 180 bottom
TP124  -  [TPAD28]  103.49 153.38 180 bottom
TP125  -  [TPAD28]  127.72 148.17 180 bottom
TP126  -  [TPAD28]  155.19 147.83 0 top
TP127  -  [TPAD28]  96.81 131.46 180 bottom
TP128  -  [TPAD28]  95.1 132.93 180 bottom
TP129  -  [TPAD28]  104.86 147.69 180 bottom
TP130  -  [TPAD28]  108.92 156 180 bottom
TP131  -  [TPAD28]  102.67 159.2 180 bottom
TP133  -  [TPAD28]  155.12 157.2 180 bottom
TP134  -  [TPAD28]  112.43 155.82 180 bottom
TP135  -  [TPAD28]  111.56 158.26 180 bottom
TP136  -  [TPAD28]  110.97 157.02 180 bottom
TP137  -  [TPAD28]  104.22 159.93 180 bottom
TP138  -  [TPAD28]  110.4 155.77 180 bottom
TP139  -  [TPAD28]  97.85 133.42 180 bottom
TP140  -  [TPAD28]  102.45 157.55 180 bottom
TP141  -  [TPAD28]  104.39 155.96 180 bottom
TP142  -  [TPAD28]  107.22 156 180 bottom
TP143  -  [TPAD28]  109.18 157.32 180 bottom
TP144  -  [TPAD28]  155.14 155.8 180 bottom
TP145  -  [TPAD28]  155.12 154.28 180 bottom
TP146  -  [TPAD28]  155.14 152.81 180 bottom
TP147  -  [TPAD28]  153.77 164.07 180 bottom
TP148  -  [TPAD28]  114.28 129.55 180 bottom
TP149  -  [TPAD28]  119.39 128.11 180 bottom
TP150  -  [TPAD28]  119.08 131.49 180 bottom
TP151  -  [TPAD28]  125.32 122.86 180 bottom
TP152  -  [TPAD28]  121.09 131.64 180 bottom
TP153  -  [TPAD28]  136.66 131.59 180 bottom
TP154  -  [TPAD28]  123.32 122.33 180 bottom
TP155  -  [TPAD28]  96.81 135.24 180 bottom
TP156  -  [TPAD28]  155.07 158.62 180 bottom
TP157  -  [TPAD28]  112.35 157.16 180 bottom
TP158  -  [TPAD28]  110.07 158.36 180 bottom
TP159  -  [TPAD28]  108.13 158.18 180 bottom
TP160  -  [TPAD28]  116.11 142.53 180 bottom
TP161  -  [TPAD28]  104.39 152.27 180 bottom
TP162  -  [TPAD28]  128.51 152.29 180 bottom
TP163  -  [TPAD28]  128.43 153.61 180 bottom
TP164  -  [TPAD28]  136.25 134.94 180 bottom
TP165  -  [TPAD28]  126.63 152.21 180 bottom
TP166  -  [TPAD28]  126.6 155.16 180 bottom
TP167  -  [TPAD28]  104.96 149.04 180 bottom
TP168  -  [TPAD28]  93.75 17.45 90 top
TP169  -  [TPAD28]  93.17 19.15 90 top
TR1  FILTER-4P-61-GP  [L2012-4P-MH56]  100.77 223.52 270 top
TR2  FILTER-4P-61-GP  [L2012-4P-MH56]  103.3 223.52 270 top
TR3  FILTER-4P-61-GP  [L2012-4P-MH56]  105.85 223.52 270 top
TR4  FILTER-4P-61-GP  [L2012-4P-MH56]  108.36 223.51 270 top
TR9  MCM1012B900FBP-GP-U  [L125100-4P-1H37]  185.29 225.81 90 top
TR10  MCM1012B900FBP-GP-U  [L125100-4P-1H37]  183.13 225.81 90 top
TR11  MCM1012B900FBP-GP-U  [L125100-4P-1H37]  171.55 211.51 270 top
TR12  MCM1012B900FBP-GP-U  [L125100-4P-1H37]  174.14 211.46 270 top
TR13  MCM1012B900FBP-GP-U  [L125100-4P-1H37]  176.46 211.46 270 top
TR14  MCM1012B900FBP-GP-U  [L125100-4P-1H37]  178.77 211.46 270 top
TR18  MCM1012B900FBP-GP-U  [L125100-4P-1H37]  177.34 67.01 90 top
TR19  MCM1012B900FBP-GP-U  [L125100-4P-1H37]  134.62 215.98 90 top
TR20  MCM1012B900FBP-GP-U  [L125100-4P-1H37]  132.38 215.98 90 top
TR22  MCM1012B900FBP-GP-U  [L125100-4P-1H37]  155.04 59 180 top
TR23  MCM1012B900FBP-GP-U  [L125100-4P-1H37]  149.73 220.24 90 top
TR24  MCM1012B900FBP-GP-U  [L125100-4P-1H37]  147.55 220.27 90 top
TR25  MCM1012B900FBP-GP-U  [L125100-4P-1H37]  155.04 61.16 180 top
TR26  MCM1012B900FBP-GP-U  [L125100-4P-1H37]  158.24 59 180 top
TR27  MCM1012B900FBP-GP-U  [L125100-4P-1H37]  158.24 61.16 180 top
U1  AZC099-04S-1-GP  [SOT-6H58]  77.98 232.16 90 top
U2  ALC662-VD-GR-GP  [LQFP48H63]  21.26 230.48 90 top
U3  2N7002DW-6-GP  [SOT-363H44]  111.12 219.84 180 top
U4  2N7002DW-6-GP  [SOT-363H44]  85.85 226.69 90 top
U6  AZC099-04S-1-GP  [SOT-6H58]  177.8 215.01 270 top
U8  NCP81161MNTBG-GP  [DFN8G2-G1309-UH40]  142.97 193.13 0 top
U9  AZC099-04S-1-GP  [SOT-6H58]  173.02 215.01 270 top
U10  SP3010-04UTG-GP  [SLP2510P8-1H22]  124 218.8 0 top
U11  AZC099-04S-1-GP  [SOT-6H58]  182.32 210.36 90 top
U12  RTL8111G-CGT-1-GP-U1  [QFN32J4-G2D9-U1H36]  169.95 206.73 270 top
U13  APL5337KAI-TRG-GP  [SOIC8-G3530H63]  64.67 80.67 270 top
U14  P2402OV-GP  [SOIC8H79]  187.66 200.91 90 top
U15  SP3010-04UTG-GP  [SLP2510P8-1H22]  129.01 221.03 0 top
U16  NCP81161MNTBG-GP  [DFN8G2-G1309-UH40]  187.63 179.04 0 top
U17  APL5611ACI-TRG-GP  [SOT-6H58]  70.99 37.21 0 top
U18  NCP81161MNTBG-GP  [DFN8G2-G1309-UH40]  86.89 198.55 90 top
U22  SSX44-B-D-T-GP  [TSOIC28-3H44]  99.46 57.6 180 top
U23  ST33ZP24AR28PVSP-D-GP  [TSOIC28H48]  99.46 57.6 180 top
U24  AZC099-04S-1-GP  [SOT-6H58]  84.2 232.16 270 top
U25  AZ1045-04F-GP  [DFN10G2510H26]  109.09 229.24 180 top
U26  AZC099-04S-1-GP  [SOT-6H58]  175.13 71.88 0 top
U27  HASWE1NFU  [SKTBGA1150R740611UH367NF]  115.5 149.5 0 top
U29  LYNX-POINT-2-GP-U  [BGA708Z2322H65]  34.76 47.03 270 top
U30CN1  SKT-SPI8P-GP-U  [ACA-SPI-004-K-U]  80.52 39.67 0 top
U31  P2402OV-GP  [SOIC8H79]  169.91 56.65 90 top
U32  AZ1045-04F-GP  [DFN10G2510H26]  105.54 229.24 180 top
U33  MX25L6406EM2I-12G-GP  [SOIC8-1H86]  80.52 39.67 180 top
U34  AZ1045-04F-GP  [DFN10G2510H26]  112.65 229.24 180 top
U35CN1  SKT-SPI8P-GP-U  [ACA-SPI-004-K-U]  90.81 39.67 0 top
U36  UZ1085G-ADJ-TN3-R-GP  [SMD-TO-252-4H94]  172.42 21.67 180 top
U39  MX25L6406EM2I-12G-GP  [SOIC8-1H86]  90.81 39.67 180 top
U47  SP3010-04UTG-GP  [SLP2510P8-1H22]  147.96 72.69 180 top
U51  APL5930KAI-TRG-1-GP  [SOIC8-G3530H63]  64.62 64.62 270 top
U52  NCP81102MNTXG-SI4-GP  [QFN32J4-G2D8-3H40]  177.34 160.86 90 top
U53  2N7002DW-6-GP  [SOT-363H44]  105.42 39.34 180 top
U61  IT8772E-EX-GP  [LQFP64H63]  99.87 14.2 90 top
UC22  SCD1U10V2KX-5GP  [C402H22]  186.69 228.35 0 top
UC62  SCD1U10V2KX-5GP  [C402H22]  136.8 218.62 270 top
UC63  SCD1U10V2KX-5GP  [C402H22]  142.49 73.74 90 top
UC75  SCD1U16V2ZY-2GP  [C402H22]  136.78 219.58 270 top
UC76  SCD1U16V2ZY-2GP  [C402H22]  152.15 219.07 270 top
UC78  SCD1U10V2KX-5GP  [C402H22]  151.61 226.57 270 top
UC79  SCD1U16V2ZY-2GP  [C402H22]  151.21 65.25 0 top
UC80  SCD1U16V2ZY-2GP  [C402H22]  150.32 65.25 0 top
UC97  15KR2J-1-GP  [R402H16]  152.4 211.58 90 top
UC103  SC1U10V3KX-3GP  [C603H36]  162.81 214.38 0 top
UC104  SCD1U10V2KX-5GP  [C402H22]  161.67 214.5 0 top
UC107  SC1KP50V2KX-1GP  [C402H22]  152.4 212.6 90 top
UC117  SC1KP50V2KX-1GP  [C402H22]  136.78 214.93 90 top
UC118  SC1KP50V2KX-1GP  [C402H22]  156.67 65.38 270 top
UC132  SCD1U16V2ZY-2GP  [C402H22]  182.63 237.49 180 top
UC133  SC1KP50V2KX-1GP  [C402H22]  188.72 227.2 0 top
UR98  10KR2J-3-GP  [R402H16]  150.88 213.11 0 top
UR99  10KR2J-3-GP  [R402H16]  136.8 217.63 270 top
UR100  10KR2J-3-GP  [R402H16]  156.67 67.41 270 top
UR106  15KR2J-1-GP  [R402H16]  136.78 215.95 90 top
UR107  15KR2J-1-GP  [R402H16]  156.67 66.4 270 top
UR108  249R2F-GP  [R402H16]  166.37 201.27 0 top
UR109  249R2F-GP  [R402H16]  167.39 201.27 0 top
UR112  330R2J-3-GP  [R402H16]  169.19 201.35 180 top
UR118  10KR2J-3-GP  [R402H16]  187.71 228.09 0 top
UR119  15KR2J-1-GP  [R402H16]  189.74 227.2 0 top
USB3R1  SKT-USB22-12-GP  [SKT-USB22-156174]  132.58 235.36 180 top
USBCN1  SKT-USB12-24-GP  [SKT-USB12-157183]  150.58 234.7 180 top
USBF1  PIN-CONN10A-SFP-2-GP  [210-92-05GB04]  174.38 77.4 0 top
USBF2  PIN-CONN10A-SFP-2-GP  [210-92-05GB04]  157 71.02 180 top
USBF3  LOTES-CONN20C-SFP-GP  [ABA-USB-050-K07]  148.35 78.35 0 top
UTC5  E220U16VM-25-GP  [ECAP-100D6D3H473]  186.94 235.97 270 top
UTC6  E220U16VM-25-GP  [ECAP-100D6D3H473]  154.94 223.01 270 top
UTC7  E220U16VM-25-GP  [ECAP-100D6D3H473]  141.6 221.11 270 top
UTC9  E220U16VM-25-GP  [ECAP-100D6D3H473]  141.83 59.13 270 top
UU12  AZC099-04S-1-GP  [SOT-6H58]  184.15 229.74 180 top
UU37  AZC099-04S-1-GP  [SOT-6H58]  153.62 65.57 0 top
UU38  AZC099-04S-1-GP  [SOT-6H58]  161.8 63.91 0 top
UU42  AZC099-04S-1-GP  [SOT-6H58]  148.5 224.24 0 top
UU43  AZC099-04S-1-GP  [SOT-6H58]  133.49 220.05 0 top
VGA1  VIDEO-15-73-GP  [DZ11AA1-H5W7-4F]  80.23 239.52 0 top
X1  XTAL-25MHZ-102-GP  [SMD49-4H56]  180.34 204.19 90 top
X2  XTAL-25MHZ-102-GP  [SMD49-4H56]  44.12 67.71 90 top
X3  XTAL-32D768KHZ-65-GP  [SMD49-6914-0403H56]  16.21 24.51 180 top
XDPC1  SMC-CONN60A-GP  [BSH-03001-FDA]  181.47 136.68 90 top

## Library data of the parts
ATX1 = C4201WV0-2-12P: tolerance: 20.80991.024
ATX12V = 1-1775099-0: tolerance: 20.80632.004
AUDF1 = T11-0061-1A40-4-U: tolerance: 21.62737.205
AUDJK1 = ABA-JAK-028-K03: tolerance: 22.10251.831
BT1 = AAA-BAT-029-P02: tolerance: 22.70034.011
BZ1 = HY-11H394: tolerance: 23.60004.051
C1 C7 C8 C11 C37 C41 C56 C57 C127 C136 C352 C353 C377 C429 C440 C469 C475 C491 C544 = C805H54: tolerance: 78.10623.51L
C2 C270 C271 C350 C387 C391 C397 C500-C504 C521 C522 C537 C542 C546-C552 C558 C560-C564 C570 C573 C574 C583-C586 = C805H58: tolerance: 78.22610.51L
C3 C4 C12 C13 C17 C31 C42 C54 C65 C71 C77 C81 C83 C85 C86 C90 C91 C93 C100 C111 C120 C132-C135 C137 C139 C141 C142 C159 C160 C172 C205 C231 C240 C254 C266 C267 C308 C355 C366 C368 C369 C376 C388 C398 C405 C406 C410 C412 C415 C417 C418 C421 C424 C435 C441 C461 C462 C478 C481 C482 C486 C489 C490 C494 C499 C505 C525 C526 C528 C541 C569 C576-C578 C580 C582 C587 C589 C591-C593 C596 C597 C599 C601 C607 C610 C614-C616 UC22 UC62 UC63 UC78 UC104 = C402H22: tolerance: 78.10423.2FL; signal model: C402H20_SCD1U10V2KX-4GP
C5 C6 C18-C21 C28 C38 C55 C60 C73 C80 C82 C92 C102 C516 PC78 = C402H22: tolerance: 78.10134.1FL
C9 C43-C50 C53 C74 C202 C315 C399 C401 C403 C430 C431 C452 C453 C456 C3325-C3327 PC352 = C402H22: tolerance: 78.10423.2FL
C14 C15 C22 C97 C112 = C402H22: tolerance: 78.10034.1FL
C16 C29 C88 C151 C187 C213 C389 C579 C612 C3324 = C603H36: tolerance: 78.47520.5BL
C23-C25 C34-C36 = C402H22: tolerance: 78.3R374.1FL
C26 C27 C126 C174 = C402H22: tolerance: 78.47124.2FL
C51 C306 C310 C460 = C603H36: tolerance: 78.22523.5BL
C59 C233 C3316-C3319 C3322 C3323 PC63 = C402H22: tolerance: 78.22034.1FL
C64 C370 C394-C396 C411 C420 C422 C433 C436 C445-C447 C451 C463 C466 C470 C472 C493 C506 C524 C527 C529 C545 C556 C557 C565 C566 C571 C572 C595 C603-C606 C611 C1669 C1671 C1673 = C402H22: tolerance: 78.10520.5FL
C70 C354 = C402H22: tolerance: 78.10322.2FL; signal model: C402H22_SCD01U16V2KX-3GP
C72 = C805H58: tolerance: 78.22523.21L
C75 C414 C438 C483 C523 C680 C1672 C3320 = C402H22: tolerance: 78.10523.5FL
C76 C373-C375 C380 C392 C393 C404 C434 C479 C496 C512 C540 C567 C568 C575 C594 C598 C600 C602 C608 C609 C613 UC75 UC76 UC79 UC80 UC132 = C402H22: tolerance: 78.10491.4FL
C89 C96 C145 C357-C364 C678 = C402H22: tolerance: 78.10322.2FL
C94 C114 = C603H36: tolerance: 78.47523.5BL
C95 C252 C382 C385 C386 C400 C402 = C402H22: tolerance: 78.10421.2FL
C103 C108 C113 C152 C157 C164 C169 C227 C407 C408 = C402H22: tolerance: 78.10422.2FL
C119 C191 C520 C581 C588 C590 C3315 = C402H20: tolerance: 78.10423.5FL; signal model: C402H20_SCD1U10V2KX-4GP
C121 C122 C124 C125 C146 C184 = C402H22: tolerance: 78.10422.2FL; signal model: C402H20_SCD1U10V2KX-4GP
C123 C144 = C805H58: tolerance: 78.10620.21L
C128 = C402H22: tolerance: 78.47224.2FL
C129 C130 C390 UC107 UC117 UC118 UC133 = C402H22: tolerance: 78.10224.2FL
C140 = C402H22: tolerance: 78.18134.1FL
C143 C198 C232 C381 PC65 PC72 = C603H36: tolerance: 78.10521.5BL
C148 C149 C158 C162 C165 C167 C173 C175 C188 C193 C207 C210 C216 C230 C244 C255 C265 C269 C279-C281 C284 C290-C292 C294-C297 C299-C301 = C402H22: tolerance: 78.22423.5FL; signal model: C402H22_SCD22U10V2KX-1GP
C153 C185 = C402H22: tolerance: 78.47034.1FL
C176 C234 C497 C498 = C402H22: tolerance: 78.22224.2FL
C177 C180 C237 = C603H36: tolerance: 78.10521.2BL
C179 C181 C200 = C1206H71: tolerance: 78.10621.22L
C183 C186 C253 C304 = C805H54: tolerance: 78.10521.21L
